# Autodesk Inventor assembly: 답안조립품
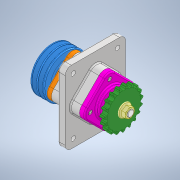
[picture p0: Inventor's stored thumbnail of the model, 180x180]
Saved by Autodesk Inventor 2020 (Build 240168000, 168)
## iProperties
Created: 2021-07
Part Number: 답안조립품
Document SubType Name: Assembly
Designer: Owner
Author: Owner
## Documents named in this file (16)
- C:\Users\Owner\Desktop\710707V1015\답안조립품.iam
- C:\Users\Owner\Desktop\710707V1015\본체.ipt
- C:\Users\Owner\Desktop\710707V1015\M16 너트.ipt
- C:\Users\Owner\Desktop\710707V1015\V-벨트풀리.ipt
- C:\Users\Owner\Desktop\710707V1015\멈춤나사 M4.ipt
- C:\Users\Owner\Desktop\710707V1015\베어링 6206.ipt
- C:\Users\Owner\Desktop\710707V1015\볼트 M6.ipt
- C:\Users\Owner\Desktop\710707V1015\부시.ipt
- C:\Users\Owner\Desktop\710707V1015\오일실 30x42x8.ipt
- C:\Users\Owner\Desktop\710707V1015\오일실 30x45x8.ipt
- C:\Users\Owner\Desktop\710707V1015\체인 스프로킷.ipt
- C:\Users\Owner\Desktop\710707V1015\축.ipt
- C:\Users\Owner\Desktop\710707V1015\커버A.ipt
- C:\Users\Owner\Desktop\710707V1015\커버B.ipt
- C:\Users\Owner\Desktop\710707V1015\키 6x6x18.ipt
- C:\Users\Owner\Desktop\710707V1015\키 6x6x20.ipt
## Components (3 placed, 2 different names)
1. M16 너트:1 — 각도:2
2. V-벨트풀리:1 — 각도:1
3. M16 너트:2 — 각도:4
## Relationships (3: Angle 3)
- 각도:1 [Angle]: V-벨트풀리:1
- 각도:2 [Angle]: M16 너트:1
- 각도:4 [Angle]: M16 너트:2
